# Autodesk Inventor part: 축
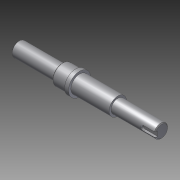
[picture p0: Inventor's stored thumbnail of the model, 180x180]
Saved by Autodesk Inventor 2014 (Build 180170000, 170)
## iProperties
Company: 한국ATC센터
Created: 2014-03
Part Number: 축
Document SubType Name: Modeling
Designer: KYOUNG IL JANG
Density: 1 g/cm^3
Material: 일반
Appearance: Default
Author: KYOUNG IL JANG
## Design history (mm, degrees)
sketch "스케치1"
  geometry: L1 (-102, 80)-(78, 80); L2 (-30.3, 106)-(-30.3, 54) reference; L3 (23, 99.7)-(23, 60.3) reference; L4 (-102, 80)-(-102, 89); L5 (-102, 89)-(-47, 89); L6 (-47, 89)-(-47, 92.5); L7 (-47, 92.5)-(-30, 92.5); L8 (-25, 94)-(-25, 91); L9 (-25, 91)-(23, 91); L10 (23, 91)-(23, 88.5); L11 (23, 88.5)-(78, 88.5); L12 (78, 88.5)-(78, 80); L13 (-30, 94)-(-25, 94); L14 (-31, 92.5)-(-44, 92.5) reference; L15 (-30, 105)-(-30, 55) reference; L16 (-30, 94)-(-30, 92.5); L17 (-68, 65.3)-(-68, 94.7) reference; L18 (-96, 89)-(-96, 85.5); L19 (-96, 85.5)-(-74, 85.5); L20 (-74, 85.5)-(-74, 89); L21 (60, 75)-(83, 75); L22 (83, 75)-(83, 71.5); L23 (83, 71.5)-(60, 71.5); L24 (60, 71.5)-(60, 75); 2 further points
  constraints: 40 end point, 12 perpendicular, 7 point on line, 3 horizontal, 3 parallel, 2 collinear, 1 midpoint, 1 other
  dimensions: "d0" = 18 diameter of L5 L1; "d1" = 17 distance of L6.end L7.end; "d2" = 5 distance of L13.start L8.start; "d3" = 28 diameter of L13 L1; "d4" = 22 diameter of L9 L1; "d5" = 17 diameter of L11 L1; "d8" = 34 distance between parallel lines of L17 L4; "d9" = 55 distance of L10.end L11.end; "d11" = 3.5 distance between parallel lines of L19 L5; "d12" = 22 distance between parallel lines of L20 L18; "d13" = 6 distance between parallel lines of L18 L4; "d14" = 17 diameter of L23 L1 (= d5); "d15" = 3.5 distance of L23.end L21.start (= d11); "d16" = 18 distance between parallel lines of L24 L12; "d17" = 23 distance of L22.end L23.end
  node "참조1"
  node "참조2"
  node "참조3"
  node "참조4"
revolve "회전1" stored, may be unused: angle "d10" = 90 deg
extrude "돌출1" cut sketch "스케치1" stored distance "d18" = 6; taper "d19" = 0 deg
fillet "모깎기1" dims "d20" = 3
chamfer "모따기1" distance "d21" = 1; stored, may be unused: second distance "d22" = 2, angle "d23" = 45 deg
node "솔리드1"
